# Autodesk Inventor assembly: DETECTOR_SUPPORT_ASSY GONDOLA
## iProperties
Shininess: 64.0
Length Units: 11272
Angle Units: 11279
Time Units: 11290
Mass Units: 11286
Length Display Precision: 3
Angle Display Precision: 2
Compacted: True
Part Number: DETECTOR_SUPPORT_ASSY GONDOLA
Document SubType Name: Assembly
Created: 2004-08
Designer: John Blackburn
Manufacturer: Standard
Standards Organization: Custom
Density: 0.0
Volumn: 0.0
Area: 0.0
PropertySet Name: Model Information
Control State: 0
Master: False
Checked Out: False
Author: John Blackburn
